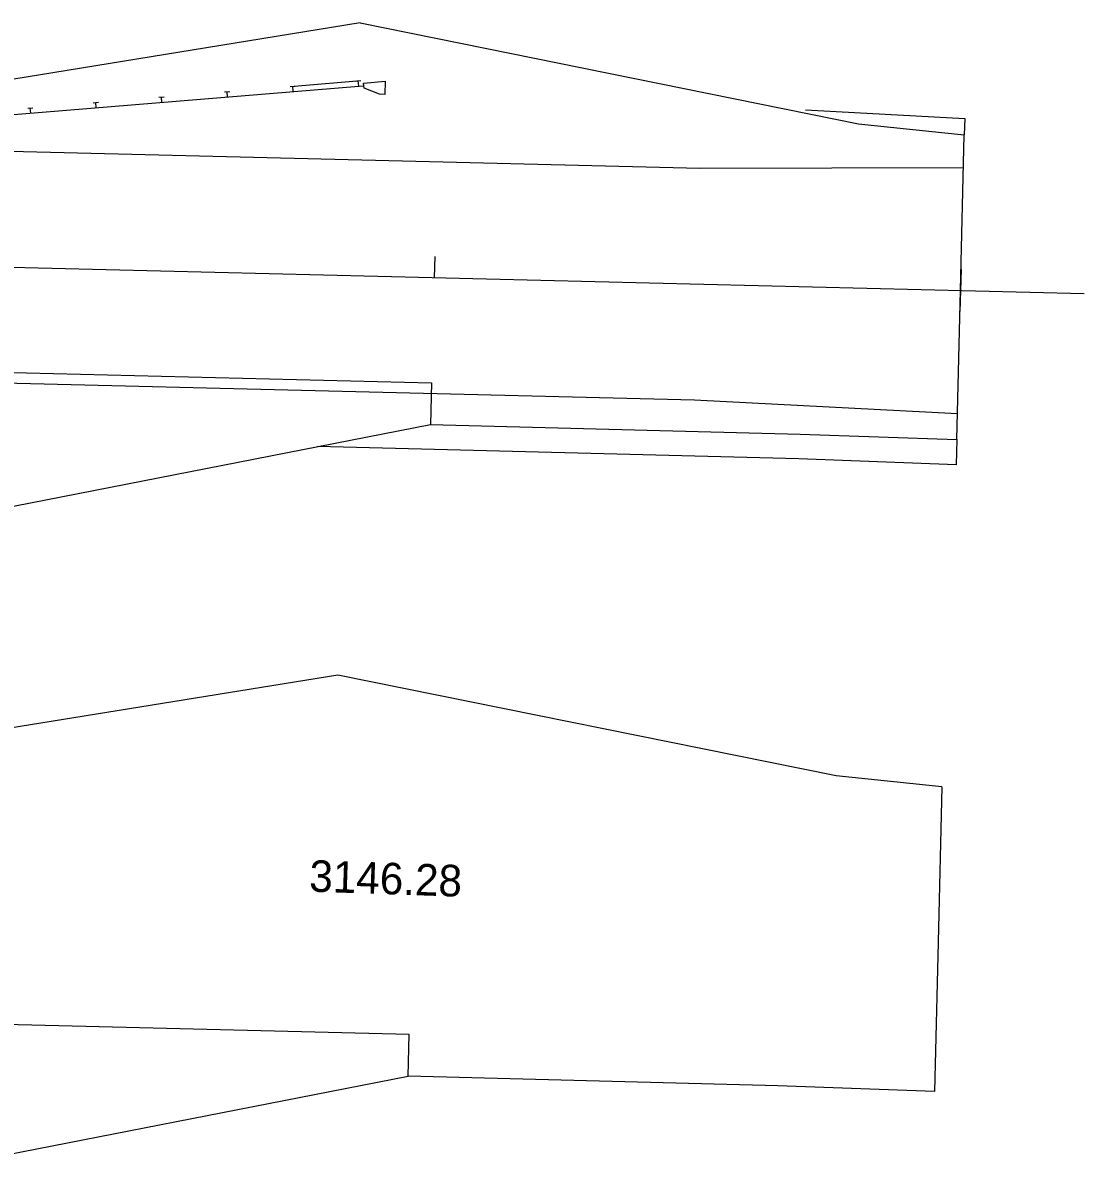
# Model space of a CAD drawing. Extents: x 2191309 to 2193046, y 863659 to 865133.
# Drawn here: x 2191828.9 to 2191929.7, y 864997 to 865105.9 of the extents above; entities that cross this region are included whole.
import ezdxf

# ---------------------------------------------------------------- set-up
doc = ezdxf.new("R2010")
doc.units = 0
for name, color, linetype in [('D_Guardrail_End_MidSplice', 7, 'Continuous'), ('D_Roadway_Centerline', 7, 'Continuous'), ('D_Roadway_Centerline_Text', 7, 'Continuous'), ('D_Roadway_Drive_Gravel', 7, 'Continuous'), ('D_Roadway_Edge_Shoulder', 7, 'Continuous'), ('FRAME', 7, 'Continuous')]:
    doc.layers.add(name, color=color, linetype=linetype)

msp = doc.modelspace()

# ---------------------------------------------------------------- linework, layer by layer
at = {"layer": 'D_Guardrail_End_MidSplice'}
for p, q in [((2191823.45, 865096.84), (2191860.83, 865099.92)), ((2191848.08, 865099.37), (2191848.58, 865099.41)), ((2191848.37, 865098.9), (2191848.33, 865099.39)), ((2191854.31, 865099.89), (2191861.03, 865100.44)), ((2191854.31, 865099.89), (2191854.81, 865099.93)), ((2191854.6, 865099.41), (2191854.56, 865099.91)), ((2191860.54, 865100.4), (2191861.03, 865100.44)), ((2191860.83, 865099.92), (2191860.79, 865100.42)), ((2191860.83, 865099.92), (2191861.33, 865099.96)), ((2191861.3, 865100.21), (2191863.34, 865100.38)), ((2191861.35, 865099.72), (2191861.3, 865100.21)), ((2191862.81, 865099.14), (2191861.35, 865099.72)), ((2191863.34, 865100.38), (2191863.31, 865099.13)), ((2191835.62, 865098.34), (2191836.12, 865098.39)), ((2191835.91, 865097.87), (2191835.87, 865098.37)), ((2191841.85, 865098.86), (2191842.35, 865098.9)), ((2191842.14, 865098.38), (2191842.1, 865098.88)), ((2191863.31, 865099.13), (2191862.81, 865099.14)), ((2191829.39, 865097.83), (2191829.89, 865097.87)), ((2191829.68, 865097.35), (2191829.64, 865097.85))]:
    msp.add_line(p, q, dxfattribs=at)
at = {"layer": 'D_Roadway_Centerline'}
msp.add_line((2191792.64, 865083.59), (2191929.72, 865080.23), dxfattribs=at)
at = {"layer": 'D_Roadway_Centerline_Text'}
for points in [[(2191868.05, 865083.74), (2191868, 865081.74)], [(2191918.04, 865082.51), (2191917.94, 865078.51)]]:
    msp.add_lwpolyline(points, dxfattribs=at)
at = {"layer": 'D_Roadway_Drive_Gravel'}
for points in [[(2191903.26, 865097.67), (2191918.39, 865096.84), (2191918.35, 865095.28)], [(2191917.64, 865066.34), (2191917.58, 865063.93), (2191902.63, 865064.53), (2191856.93, 865065.69)]]:
    msp.add_lwpolyline(points, dxfattribs=at)
at = {"layer": 'D_Roadway_Edge_Shoulder'}
for p, q in [((2191860.97, 865105.92), (2191823.53, 865099.84)), ((2191917.99, 865080.51), (2191918.35, 865095.28)), ((2191917.64, 865066.34), (2191917.99, 865080.51)), ((2191821.4, 865037.93), (2191858.85, 865044.01)), ((2191916.23, 865033.37), (2191915.86, 865018.61)), ((2191915.86, 865018.61), (2191915.52, 865004.43))]:
    msp.add_line(p, q, dxfattribs=at)
for points in [[(2191860.97, 865105.92), (2191908.29, 865096.34), (2191918.35, 865095.28)], [(2191792.96, 865094.59), (2191893.27, 865092.12), (2191918.28, 865092.19)], [(2191767.46, 865067.45), (2191767.69, 865074.2), (2191867.76, 865071.74), (2191867.66, 865067.78)], [(2191792.31, 865072.6), (2191892.73, 865070.13), (2191917.7, 865068.83)], [(2191822.02, 865058.86), (2191867.66, 865067.78), (2191902.76, 865066.86), (2191917.64, 865066.34)], [(2191858.85, 865044.01), (2191906.17, 865034.43), (2191916.22, 865033.38)], [(2191865.54, 865005.87), (2191865.63, 865009.84), (2191815.65, 865011.06)], [(2191819.89, 864996.95), (2191865.54, 865005.87)], [(2191915.51, 865004.43), (2191900.63, 865004.95), (2191865.54, 865005.87)]]:
    msp.add_lwpolyline(points, dxfattribs=at)

# ---------------------------------------------------------------- texts
at = {"layer": 'FRAME'}
msp.add_text('3146.28', height=3, rotation=358.0343, dxfattribs=at).set_placement((2191856.1, 865023.41))

doc.saveas('drawing.dxf')
